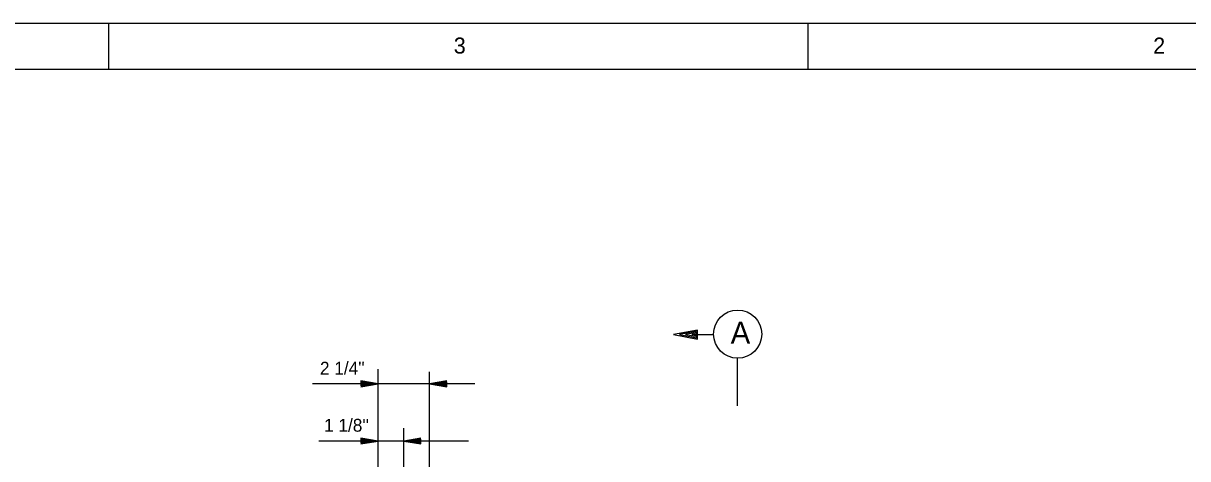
# Model space of a CAD drawing. Extents: x 0 to 13.3, y 0 to 9.3.
# Drawn here: x 5.231 to 9.463, y 7.75 to 9.333 of the extents above; entities that cross this region are included whole.
import ezdxf

# ---------------------------------------------------------------- set-up
doc = ezdxf.new("R2010")
doc.units = 0
doc.layers.add('Level 1', color=7, linetype='Continuous')
doc.layers.add('Level 3', color=7, linetype='Continuous')

msp = doc.modelspace()

# ---------------------------------------------------------------- linework, layer by layer
at = {"layer": 'Level 1'}
for p, q in [((5.5417, 9.1667), (5.5417, 9.3333)), ((8.0833, 9.1667), (8.0833, 9.3333))]:
    msp.add_line(p, q, dxfattribs=at)
for points in [[(0, 9.3333), (13.3333, 9.3333), (13.3333, 0), (0, 0)], [(0.5, 9.1667), (13.1667, 9.1667), (13.1667, 0.1667), (0.5, 0.1667)]]:
    msp.add_lwpolyline(points, close=True, dxfattribs=at)
at = {"layer": 'Level 3'}
for p, q in [((7.6814, 8.2013), (7.7397, 8.2013)), ((7.8272, 7.9418), (7.8272, 8.1139)), ((6.5202, 7.2337), (6.5202, 8.0753)), ((6.7078, 7.2337), (6.7078, 8.0657)), ((6.5202, 8.0221), (6.2825, 8.0221)), ((6.5029, 8.0221), (6.5029, 8.0221)), ((6.7078, 8.0221), (6.5202, 8.0221)), ((6.5202, 8.0221), (6.5202, 8.0221)), ((6.8717, 8.0221), (6.7078, 8.0221)), ((6.7078, 8.0221), (6.7078, 8.0221)), ((6.7252, 8.0221), (6.7252, 8.0221)), ((6.614, 7.3073), (6.614, 7.8609)), ((6.5202, 7.8137), (6.3047, 7.8137)), ((6.5029, 7.8137), (6.5029, 7.8137)), ((6.614, 7.8137), (6.5202, 7.8137)), ((6.5202, 7.8137), (6.5202, 7.8137)), ((6.8493, 7.8137), (6.614, 7.8137)), ((6.614, 7.8137), (6.614, 7.8137)), ((6.6314, 7.8137), (6.6314, 7.8137))]:
    msp.add_line(p, q, dxfattribs=at)
for points in [[(7.6814, 8.2135), (7.6814, 8.2179), (7.5939, 8.2013), (7.6814, 8.1849), (7.6814, 8.2135), (7.6162, 8.2016), (7.6771, 8.1899), (7.6771, 8.2087), (7.6382, 8.2016), (7.6731, 8.195), (7.6731, 8.2038), (7.6605, 8.2016), (7.6688, 8.2)], [(6.4579, 8.0118), (6.5202, 8.0221), (6.4579, 8.0325), (6.4579, 8.0148), (6.5029, 8.0221), (6.4605, 8.0291), (6.4605, 8.0178), (6.4862, 8.0221), (6.4632, 8.0258), (6.4632, 8.0211), (6.4689, 8.0221)], [(6.7702, 8.0325), (6.7078, 8.0221), (6.7702, 8.0118), (6.7702, 8.0295), (6.7252, 8.0221), (6.7675, 8.0151), (6.7675, 8.0265), (6.7418, 8.0221), (6.7648, 8.0185), (6.7648, 8.0231), (6.7592, 8.0221)], [(6.4579, 7.8034), (6.5202, 7.8137), (6.4579, 7.824), (6.4579, 7.8064), (6.5029, 7.8137), (6.4605, 7.8207), (6.4605, 7.8094), (6.4862, 7.8137), (6.4632, 7.8174), (6.4632, 7.8127), (6.4689, 7.8137)], [(6.6764, 7.824), (6.614, 7.8137), (6.6764, 7.8034), (6.6764, 7.821), (6.6314, 7.8137), (6.6737, 7.8067), (6.6737, 7.818), (6.648, 7.8137), (6.6711, 7.81), (6.6711, 7.8147), (6.6654, 7.8137)]]:
    msp.add_lwpolyline(points, dxfattribs=at)
msp.add_circle((7.8272, 8.203), 0.0875, dxfattribs=at)

# ---------------------------------------------------------------- texts
at = {"layer": 'Level 1'}
for s, p in [('3', (6.7956, 9.2231)), ('2', (9.3373, 9.223))]:
    msp.add_text(s, height=0.0584, dxfattribs=at).set_placement(p)
at = {"layer": 'Level 3'}
for s, height, p in [('A', 0.08, (7.8017, 8.168)), ("2 1/4''", 0.04669, (6.3093, 8.0557)), ("1 1/8''", 0.04669, (6.3245, 7.8482))]:
    msp.add_text(s, height=height, dxfattribs=at).set_placement(p)

doc.saveas('drawing.dxf')
